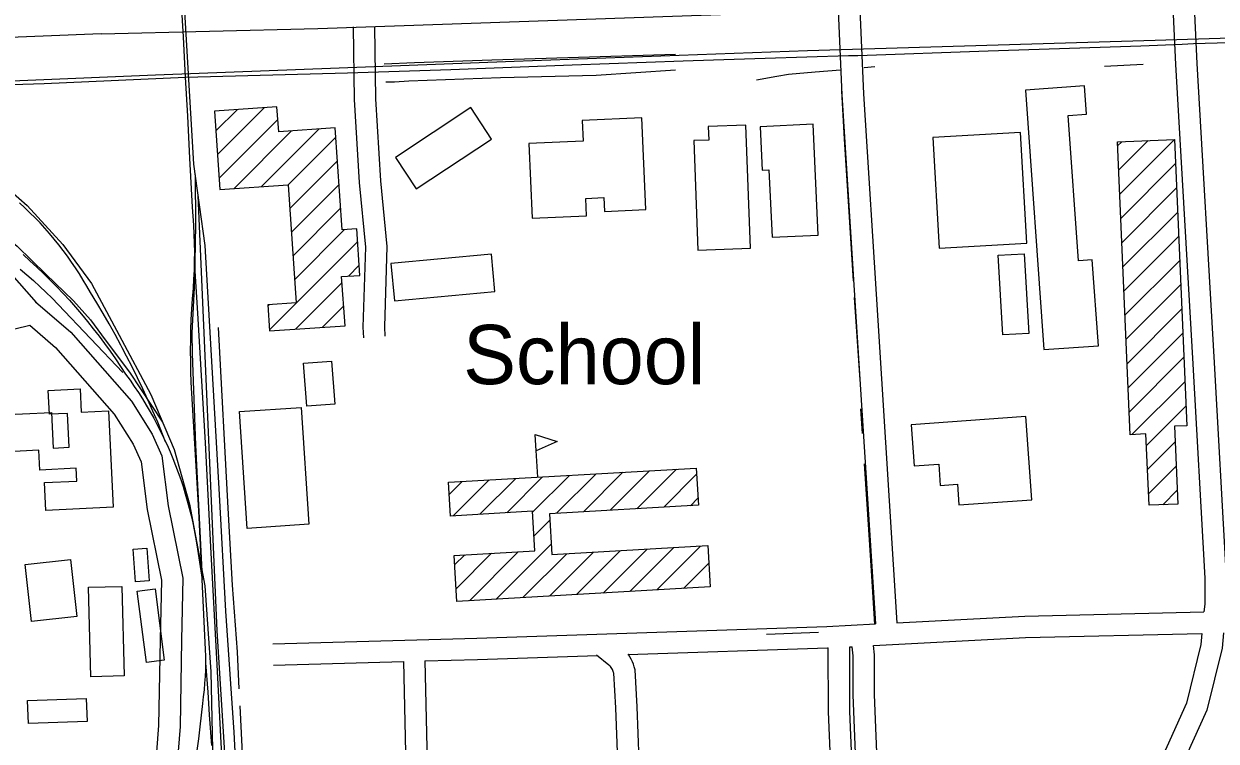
# Model space of a CAD drawing. Extents: x 3313447 to 3351316, y 703786 to 729172.
# Drawn here: x 3330361 to 3332031, y 715337 to 716341 of the extents above; entities that cross this region are included whole.
import ezdxf

# ---------------------------------------------------------------- set-up
doc = ezdxf.new("R2010")
doc.units = 0
for name, color, linetype in [('V-BLDG-IDEN', 7, 'Continuous'), ('V-BLDG-OTLN', 7, 'Continuous'), ('V-RAIL-TRAK', 7, 'Continuous'), ('V-ROAD-CNTR', 7, 'Continuous'), ('V-TOPO-SHOR', 7, 'Continuous')]:
    doc.layers.add(name, color=color, linetype=linetype)

msp = doc.modelspace()

# ---------------------------------------------------------------- linework, layer by layer
at = {"layer": 'V-BLDG-OTLN'}
for p, q in [((3330629.8, 716191.6), (3330659.9, 716221.7)), ((3330632.1, 716158.6), (3330697.8, 716224.3)), ((3330634.4, 716125.5), (3330716.6, 716207.7)), ((3330655.2, 716110.9), (3330735.8, 716191.6)), ((3330693.2, 716113.5), (3330773.8, 716194.2)), ((3330731.1, 716116.1), (3330797.7, 716182.8)), ((3331893.1, 716170.6), (3331898.9, 716176.5)), ((3331894.5, 716136.8), (3331935.8, 716178.1)), ((3331896, 716102.9), (3331972.8, 716179.7)), ((3330733.4, 716083.1), (3330800, 716149.7)), ((3331897.5, 716069), (3331974.3, 716145.8)), ((3330735.7, 716050), (3330802.3, 716116.6)), ((3331898.9, 716035.1), (3331975.7, 716111.9)), ((3330737.9, 716016.9), (3330804.6, 716083.5)), ((3331900.4, 716001.2), (3331977.2, 716078)), ((3330740.2, 715983.8), (3330809.6, 716053.2)), ((3330704.9, 715913.2), (3330828.3, 716036.5)), ((3331901.9, 715967.3), (3331978.7, 716044.1)), ((3330815.4, 715988.3), (3330830.6, 716003.5)), ((3331903.4, 715933.5), (3331980.2, 716010.2)), ((3330741.3, 715914.2), (3330806.5, 715979.4)), ((3331904.8, 715899.6), (3331981.6, 715976.4)), ((3330702.6, 715946.2), (3330704.6, 715948.2)), ((3330779.2, 715916.8), (3330808.8, 715946.3)), ((3331906.3, 715865.7), (3331983.1, 715942.5)), ((3331907.8, 715831.8), (3331984.6, 715908.6)), ((3331909.2, 715797.9), (3331986, 715874.7)), ((3331913.2, 715766.5), (3331987.5, 715840.8)), ((3331933.5, 715751.4), (3331989, 715806.9)), ((3331080.8, 715706.9), (3331077.3, 715766.8)), ((3331934.9, 715717.5), (3331973.8, 715756.4)), ((3331144.7, 715658.4), (3331200, 715713.7)), ((3331182.2, 715660.5), (3331237.5, 715715.8)), ((3331219.7, 715662.7), (3331275, 715718)), ((3331936.4, 715683.7), (3331975.3, 715722.5)), ((3330956.8, 715682.7), (3330975, 715700.9)), ((3330962.2, 715652.7), (3331012.5, 715703)), ((3330999.7, 715654.9), (3331050, 715705.2)), ((3331037.2, 715657), (3331087.5, 715707.3)), ((3331073.5, 715657.9), (3331125, 715709.4)), ((3331107.2, 715656.3), (3331162.5, 715711.6)), ((3331257.2, 715664.8), (3331303.3, 715710.9)), ((3331956.5, 715668.4), (3331976.7, 715688.6)), ((3331294.7, 715666.9), (3331305.2, 715677.5)), ((3331075.4, 715624.5), (3331097.9, 715647)), ((3331022.4, 715536.2), (3331099.8, 715613.5)), ((3330964.3, 715584.1), (3330978.5, 715598.3)), ((3330966.2, 715550.6), (3331016, 715600.4)), ((3330985, 715534), (3331053.5, 715602.5)), ((3331059.9, 715538.3), (3331121.5, 715599.8)), ((3331097.4, 715540.4), (3331159, 715602)), ((3331134.9, 715542.6), (3331196.5, 715604.1)), ((3331172.4, 715544.7), (3331234, 715606.2)), ((3331209.9, 715546.8), (3331271.5, 715608.4)), ((3331247.4, 715549), (3331308.9, 715610.5)), ((3331284.9, 715551.1), (3331320.5, 715586.7))]:
    msp.add_line(p, q, dxfattribs=at)
for points in [[(3331764.1, 716248.9), (3331789.7, 715885.6), (3331866.1, 715891), (3331857.6, 716011.2), (3331838.2, 716009.8), (3331823.9, 716213.2), (3331849.3, 716215), (3331846.5, 716254.7)], [(3330731.1, 716116.1), (3330742.5, 715950.8), (3330702.5, 715948.1), (3330705, 715911.7), (3330810.7, 715918.9), (3330806, 715987.6), (3330831.5, 715989.4), (3330827.1, 716054.4), (3330806.7, 716053), (3330796.9, 716195.8), (3330717.8, 716190.3), (3330715.4, 716225.5), (3330627.9, 716219.5), (3330635.5, 716109.6)], [(3330910.3, 716110.5), (3331015.9, 716180.2), (3330986.9, 716224.2), (3330881.2, 716154.5)], [(3331068.3, 716173.8), (3331073.1, 716069.3), (3331149, 716072.7), (3331147.9, 716097), (3331173.1, 716098.2), (3331174, 716079), (3331232.3, 716081.6), (3331226.5, 716210.1), (3331143.1, 716206.4), (3331144.4, 716177.3)], [(3331378.7, 716027.5), (3331372.4, 716199.8), (3331319.6, 716197.9), (3331320.3, 716178.8), (3331299.2, 716178), (3331304.8, 716024.7)], [(3331473.6, 716045.7), (3331466.4, 716200.9), (3331392.2, 716197.5), (3331395.1, 716136.7), (3331404.5, 716137.1), (3331408.9, 716042.7)], [(3331634.3, 716182.2), (3331643.2, 716027.5), (3331765.9, 716034.5), (3331757.1, 716189.2)], [(3331972.8, 716179.7), (3331990.2, 715779), (3331972.8, 715778.3), (3331977.6, 715669.3), (3331937.1, 715667.6), (3331932.8, 715767.4), (3331910.6, 715766.4), (3331892.8, 716176.2)], [(3331015.7, 716019), (3330875.1, 716006.1), (3330879.8, 715954), (3331020.4, 715966.9)], [(3331762.2, 716019.6), (3331768.7, 715908.2), (3331732.2, 715906.1), (3331725.6, 716017.5)], [(3330791.9, 715869.4), (3330796.4, 715809.1), (3330757.2, 715806.1), (3330752.7, 715866.5)], [(3330479.3, 715799.9), (3330485.7, 715664.8), (3330391.5, 715660.4), (3330389.7, 715699.3), (3330435, 715701.4), (3330434.1, 715719.3), (3330383.2, 715716.9), (3330381.9, 715744.6), (3330320.2, 715741.6), (3330317.7, 715793.7), (3330399.4, 715797.6), (3330401.7, 715747.7), (3330424.1, 715748.7), (3330421.8, 715796.2), (3330396.5, 715795), (3330394.9, 715828.3), (3330439.5, 715830.4), (3330441, 715798.1)], [(3330749.1, 715804.3), (3330759.8, 715640.9), (3330673.8, 715635.2), (3330663.1, 715798.7)], [(3331764.6, 715791.7), (3331604, 715780.4), (3331608, 715722.8), (3331642.5, 715725.2), (3331644.6, 715695.4), (3331668.8, 715697.2), (3331670.8, 715668.1), (3331772.8, 715675.3)], [(3331077.3, 715766.8), (3331107.9, 715757), (3331078.7, 715743.7)], [(3331322.4, 715553.2), (3330967.2, 715533), (3330963.6, 715597.4), (3331076.6, 715603.8), (3331073.5, 715659.1), (3330958.5, 715652.5), (3330955.8, 715699.8), (3331302.8, 715719.6), (3331305.8, 715667.6), (3331097.4, 715655.7), (3331100.6, 715598.6), (3331319.1, 715611.1)], [(3330533.2, 715607.5), (3330536.5, 715561.6), (3330517.3, 715560.2), (3330513.9, 715606.1)], [(3330434.8, 715511.9), (3330371.3, 715505.1), (3330362.7, 715584.8), (3330426.2, 715591.7)], [(3330498.1, 715554.1), (3330501.5, 715428.8), (3330454.5, 715427.5), (3330451.2, 715552.9)], [(3330532.5, 715447.7), (3330519.6, 715547.5), (3330544.6, 715550.7), (3330557.5, 715450.9)], [(3330449.5, 715365), (3330367.3, 715362), (3330366.1, 715394.1), (3330448.3, 715397.2)]]:
    msp.add_lwpolyline(points, close=True, dxfattribs=at)
at = {"layer": 'V-RAIL-TRAK'}
for points in [[(3330593.5, 716153.3), (3330590.5, 716212.3), (3330587.3, 716266.9), (3330584.2, 716323.2), (3330580.9, 716384.7), (3330572.3, 716551.1), (3330563.2, 716723.3), (3330553.6, 716910.6), (3330540.9, 717131.4), (3330532.3, 717284.4), (3330525.8, 717402.3)], [(3331327.1, 716291.1), (3331399.5, 716293.7), (3331515.9, 716297), (3331528.9, 716297.3), (3331711.9, 716303.8), (3331925.4, 716310.9), (3331983.3, 716313.2), (3331999.2, 716313.8), (3332115.3, 716317.4), (3332296.2, 716323.8), (3332449.3, 716328.8), (3332625.3, 716333.2), (3332792.9, 716339.6), (3332872.2, 716341.7), (3333031.8, 716348.2), (3333212, 716354), (3333230.6, 716354.7)], [(3329912, 716242.8), (3329923.2, 716243.2), (3330166, 716250.9), (3330389, 716258.1), (3330587.3, 716266.9), (3330814, 716273), (3330959.1, 716277.5), (3331128.9, 716284.1)], [(3331128.9, 716284.1), (3331284.2, 716289.6), (3331327.1, 716291.1)], [(3330603.8, 715324.4), (3330606, 715340.8), (3330608, 715357.2), (3330609.8, 715373.7), (3330611.4, 715390.2), (3330612.6, 715399.6), (3330613.7, 715409), (3330614.5, 715418.5), (3330615.1, 715427.9), (3330615.5, 715437.4), (3330615.6, 715446.9), (3330615.6, 715447.2), (3330615.6, 715447.2), (3330615.6, 715456.4), (3330615.3, 715465.9), (3330614.9, 715475.4), (3330610.8, 715563.7), (3330605.8, 715660), (3330595.4, 715839.8), (3330594.8, 715854.4), (3330594.5, 715869.1), (3330594.4, 715883.7), (3330594.5, 715898.3), (3330594.9, 715913), (3330595.4, 715927.6), (3330596.2, 715942.2), (3330597.2, 715956.8), (3330598.4, 715971.4), (3330599.1, 715984), (3330599.7, 715996.6), (3330600, 716009.2), (3330600, 716010.1), (3330600.1, 716021.8), (3330599.9, 716034.4), (3330599.5, 716047), (3330598.9, 716059.6), (3330598, 716072.2), (3330596.9, 716084.7), (3330593.5, 716153.3)], [(3330559.4, 715756.5), (3330548.4, 715783.7), (3330541.6, 715799.4), (3330534.6, 715815), (3330527.5, 715830.5), (3330520.1, 715845.9), (3330512.5, 715861.2), (3330504.8, 715876.4), (3330498.6, 715888.1), (3330496.8, 715891.5), (3330488.6, 715906.5), (3330480.3, 715921.4), (3330471.8, 715936.2), (3330463.1, 715950.9), (3330454.1, 715965.4), (3330449.2, 715974.2), (3330444.1, 715982.8), (3330438.8, 715991.4), (3330433.3, 715999.8), (3330427.7, 716008.1), (3330421.8, 716016.3), (3330415.8, 716024.4), (3330409.7, 716032.3), (3330403.3, 716040.2), (3330396.8, 716047.8), (3330390.2, 716055.4), (3330383.4, 716062.8), (3330376.4, 716070), (3330369.3, 716077.1), (3330362, 716084), (3330354.6, 716090.8)], [(3330359.6, 716018.4), (3330369.3, 716009.8), (3330378.9, 716000.9), (3330388.4, 715992), (3330397.6, 715982.8), (3330406.8, 715973.5), (3330415.7, 715964.1), (3330424.5, 715954.5), (3330433.2, 715944.8), (3330441.7, 715934.9), (3330450, 715924.9), (3330458.1, 715914.7), (3330466.1, 715904.4), (3330473.9, 715894), (3330481.6, 715883.5), (3330489, 715872.8), (3330496.3, 715862), (3330503.4, 715851.1), (3330509.5, 715842.6), (3330515.4, 715834), (3330521.2, 715825.3), (3330526.9, 715816.5), (3330532.3, 715807.6), (3330537.6, 715798.6), (3330542.7, 715789.5), (3330547.6, 715780.3), (3330552.4, 715771), (3330557, 715761.6), (3330559.4, 715756.5), (3330561.4, 715752.1), (3330565.6, 715742.6), (3330569.6, 715732.9), (3330573.4, 715723.2), (3330577.1, 715713.4), (3330580.6, 715703.6), (3330583.8, 715693.7)], [(3330355.8, 715997.9), (3330365, 715990.1), (3330374.1, 715982.1), (3330383, 715974), (3330391.8, 715965.8), (3330400.4, 715957.3), (3330408.9, 715948.7), (3330499.6, 715853.4)], [(3330653.8, 715026.9), (3330649.7, 715122.8), (3330642.4, 715241.9), (3330636.5, 715344.1), (3330631.5, 715444), (3330622.9, 715609.5), (3330615.2, 715754.9), (3330608.4, 715873.1), (3330604.7, 715936.5), (3330600, 716010.1)], [(3330583.8, 715693.7), (3330586.9, 715683.7), (3330589.8, 715673.7), (3330592.5, 715663.6), (3330595, 715653.4), (3330597.3, 715643.2), (3330599.4, 715633), (3330601.3, 715622.7), (3330603, 715612.4), (3330610.8, 715563.7)], [(3330624.1, 715331.1), (3330620.9, 715374.4), (3330619.1, 715406.1), (3330615.6, 715447.2), (3330615.6, 715447.2)]]:
    msp.add_lwpolyline(points, dxfattribs=at)
at = {"layer": 'V-ROAD-CNTR'}
for points in [[(3330677.1, 714992.6), (3330666, 715141.2), (3330655.4, 715349.9), (3330643.7, 715519.4), (3330635, 715682.7), (3330614.9, 716031), (3330599.1, 716145), (3330582.7, 716422.4), (3330568.6, 716732.9)], [(3329861.3, 716250.6), (3330175.9, 716254.8), (3330545.3, 716270.2), (3331047.9, 716289.4), (3331458.4, 716304.2), (3331945.8, 716318.6), (3332309.5, 716330), (3332780.8, 716344.3), (3333213.8, 716359.9), (3333602.5, 716373.4), (3334251, 716393.9), (3334842.9, 716415.2), (3335181.3, 716429.3), (3335305.5, 716433.6), (3335413.4, 716430.4), (3335611.4, 716415.4), (3335694.4, 716414.5), (3335953.5, 716431.2), (3336497.3, 716445.2), (3336959.2, 716465.4), (3337670.9, 716480.6), (3338166, 716495.7)], [(3330469.3, 716327.4), (3330772.5, 716335.2), (3331645.6, 716365.3), (3332095, 716379.1), (3332695, 716402.4), (3333117.2, 716413.5), (3333204.7, 716416.3)], [(3331969.8, 716375), (3331974.2, 716284.4), (3331998, 715873.6), (3332015.1, 715565.5), (3332015.1, 715529.3), (3332014, 715518.2)], [(3331999.7, 716376.5), (3332004.2, 716286), (3332027.9, 715875.3), (3332045.1, 715566.4), (3332045.1, 715527.9), (3332044.2, 715518.9)], [(3331501.8, 716360.3), (3331506.9, 716242.1), (3331527, 715924.4), (3331553.9, 715501.4)], [(3331531.8, 716361.5), (3331536.9, 716243.7), (3331557, 715926.3), (3331583.9, 715502.9)], [(3330821.9, 716337.2), (3330823.6, 716235.6), (3330830.3, 716119.2), (3330839.4, 716028.8), (3330835.7, 715916.8), (3330836.8, 715902.1)], [(3330851.9, 716337.7), (3330853.6, 716236.7), (3330860.2, 716121.6), (3330869.5, 716029.8), (3330865.8, 715917.4), (3330866.7, 715904.4)], [(3330469.3, 716327.4), (3326509.4, 716168.5)], [(3329346.3, 716210.2), (3329543.1, 716225.4), (3329607.2, 716232.6), (3329846.2, 716250.8), (3329918.9, 716250), (3329981.1, 716247), (3330060.3, 716235), (3330129.5, 716221.4), (3330174.9, 716209.4), (3330230.6, 716183.6), (3330330.4, 716118.2), (3330365.2, 716087.3), (3330415.6, 716032.7), (3330455.4, 715977.9), (3330494.2, 715905.8), (3330538.6, 715822.7), (3330571.5, 715745.8), (3330592.7, 715669), (3330614.5, 715554.9), (3330622.8, 715434.4), (3330625.6, 715304.4)], [(3329652.3, 716205.3), (3329742.5, 716211.3), (3329790, 716215.8), (3329862.4, 716219.7), (3329908.2, 716217.3), (3329939.1, 716214.7), (3329975.1, 716210.8), (3330006.5, 716209), (3330055, 716200.3), (3330071.9, 716196.7), (3330112.3, 716182.1), (3330148.1, 716165.8), (3330191.2, 716145.7), (3330219, 716129.2), (3330264.6, 716101), (3330308.9, 716065.8), (3330351.2, 716030.5), (3330391.8, 715991.1), (3330430.3, 715954), (3330454.3, 715927.4), (3330474.5, 715899.3), (3330508.9, 715854.1), (3330555.2, 715783.8)], [(3330610.6, 715575.3), (3330601.5, 715751.9), (3330597.1, 715880.2), (3330596.6, 715909.1), (3330600.3, 715981.1), (3330601.5, 716060.6), (3330601.2, 716130.3)], [(3330659.5, 715023.2), (3330647.9, 715231.9), (3330631.6, 715491.6), (3330605.2, 716101.1)], [(3330378.4, 715951.6), (3330340.9, 715994)], [(3330377.2, 715952.2), (3330426.4, 715909.9), (3330511.6, 715813.2), (3330540.6, 715767.2), (3330554.3, 715736.6), (3330563, 715666.7), (3330583.5, 715565.4), (3330581.8, 715478.7), (3330579.6, 715358.1), (3330573.2, 715277.3)], [(3330241.2, 715900.3), (3330307.5, 715904.9), (3330369.2, 715919.5), (3330405.3, 715888.5), (3330487.5, 715795.2), (3330514.1, 715753), (3330525.1, 715728.4), (3330533.4, 715661.8), (3330553.4, 715562.7), (3330551.8, 715479.3), (3330549.6, 715359.5), (3330543.2, 715279.6), (3330536.9, 715193), (3330529.2, 715130.5), (3330508.1, 715080.6), (3330501.6, 715032.7), (3330483.8, 714960.7), (3330460, 714828.5), (3330442.8, 714755.8), (3330432.7, 714718.3), (3330411, 714694.2), (3330389.8, 714682.5), (3330355.9, 714674.1), (3330335.9, 714672.7)], [(3331583.9, 715502.9), (3331762.9, 715512.3), (3332014, 715518.2)], [(3330709.7, 715473.8), (3330995.2, 715481.7), (3331485.5, 715497.8), (3331553.9, 715501.4)], [(3331551.2, 715471.2), (3331764, 715482.3), (3332011.2, 715488.1)], [(3332011.2, 715488.1), (3332009.7, 715472.6), (3331989.4, 715390.6), (3331961.8, 715329.3), (3331894.9, 715182.2), (3331862.6, 715110.1), (3331852, 715049.1), (3331843.2, 714999), (3331838.6, 714928.2), (3331843.4, 714766.3), (3331850.4, 714637.7), (3331850.8, 714610)], [(3332041.4, 715488.9), (3332039.4, 715467.5), (3332017.9, 715380.8), (3331989.1, 715316.9), (3331922.3, 715169.8), (3331891.5, 715101.3), (3331881.6, 715043.9), (3331873.1, 714995.5), (3331868.7, 714927.7), (3331873.3, 714767.5), (3331880.4, 714638.7), (3331880.8, 714610.9)], [(3331207.1, 715458.6), (3331486.8, 715467.8), (3331487.7, 715467.9)], [(3331517.1, 714598.9), (3331512.9, 714793.7), (3331488, 715378.2), (3331487.7, 715467.9)], [(3331517.7, 715469.4), (3331521.2, 715469.6)], [(3331547.1, 714599.9), (3331542.9, 714794.6), (3331518, 715378.9), (3331517.7, 715469.4)], [(3331555.4, 714600.2), (3331544.9, 714843.7), (3331522.5, 715402.1), (3331522.5, 715456.6), (3331521.2, 715469.6)], [(3331585.4, 714601.2), (3331574.9, 714845), (3331552.5, 715402.7), (3331552.5, 715458.1), (3331551.2, 715471.2)], [(3330710.6, 715443.8), (3330892.7, 715448.8)], [(3330892.7, 715448.8), (3330903.1, 714981.8), (3330920.4, 714576.1)], [(3330922.6, 715449.7), (3330996.1, 715451.7), (3331164.5, 715457.2)], [(3330922.6, 715449.7), (3330933.1, 714982.8), (3330950.3, 714577.7)], [(3331220.5, 714588.3), (3331217.9, 714648), (3331213.6, 714740.4), (3331209.7, 714830.2), (3331205.7, 714906.3), (3331203.3, 714994.4), (3331200.9, 715104.5), (3331196.6, 715201.9), (3331193, 715309.9), (3331190.3, 715384), (3331187.2, 715432.7), (3331187, 715433.6), (3331186.6, 715435), (3331186, 715436.5), (3331185.3, 715437.9), (3331184.5, 715439.2), (3331183.6, 715440.5), (3331182.7, 715441.7), (3331181.6, 715442.8), (3331180.5, 715443.8), (3331162.8, 715457.7)], [(3331250.5, 714588.9), (3331247.9, 714649.3), (3331243.6, 714741.8), (3331239.6, 714831.6), (3331235.7, 714907.5), (3331233.3, 714995.1), (3331230.9, 715105.5), (3331226.6, 715203.1), (3331223, 715310.9), (3331220.2, 715385.5), (3331217, 715437.1), (3331216, 715441.5), (3331214.8, 715445.1), (3331213.4, 715448.6), (3331211.8, 715452.1), (3331209.8, 715455.3), (3331207.7, 715458.5), (3331207.5, 715458.6)]]:
    msp.add_lwpolyline(points, dxfattribs=at)
at = {"layer": 'V-TOPO-SHOR'}
for p, q in [((3331553, 716281.2), (3331538, 716279.9)), ((3331928.8, 716284.4), (3331874.5, 716282)), ((3331532.5, 715843.3), (3331524.3, 715958.3)), ((3331535.8, 715767.9), (3331533.2, 715802.6)), ((3331474, 715489.4), (3331401.3, 715486.7))]:
    msp.add_line(p, q, dxfattribs=at)
for points in [[(3330865.5, 716285.5), (3330908, 716287.5), (3331016.4, 716291.1), (3331122.9, 716294.5), (3331273.9, 716299)], [(3331273.9, 716276.7), (3331162.6, 716269.2), (3331028.4, 716265.9), (3330899.9, 716261.1), (3330879.8, 716259.8), (3330867.8, 716259.7)], [(3331505, 716276.9), (3331469.2, 716273.8), (3331432.2, 716270.7), (3331415.7, 716267.7), (3331387.4, 716262.6)], [(3331523, 715981.9), (3331516.8, 716078.5), (3331510.5, 716179.9), (3331506.7, 716247.8)], [(3330662.6, 715410.4), (3330660.3, 715462.3), (3330653.3, 715555.7), (3330646.9, 715663.5), (3330633.3, 715916.5)], [(3331552.9, 715500.5), (3331548.1, 715576.4), (3331542.3, 715669.1), (3331538.4, 715725.7)], [(3330687.9, 714932.8), (3330678.2, 715085.9), (3330673.7, 715185.8), (3330663.8, 715386.9)]]:
    msp.add_lwpolyline(points, dxfattribs=at)

# ---------------------------------------------------------------- texts
at = {"layer": 'V-BLDG-IDEN'}
msp.add_text('School', height=83, dxfattribs=at).set_placement((3330976.2, 715837.1))

doc.saveas('drawing.dxf')
